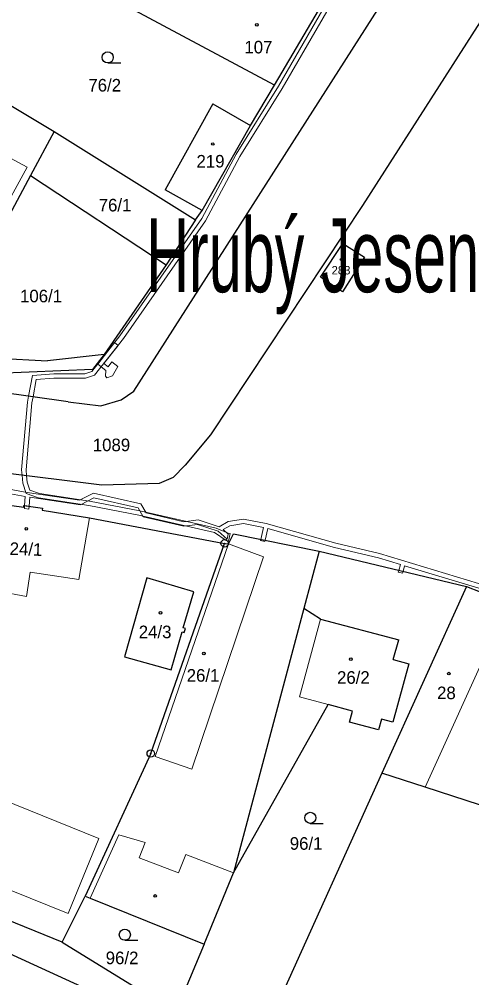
# Model space of a CAD drawing. Extents: x -694609 to -690140, y -1033292 to -1029794.
# Drawn here: x -692957.6 to -692896.4, y -1031318.8 to -1031189.2 of the extents above; entities that cross this region are included whole.
import ezdxf
from ezdxf.enums import TextEntityAlignment as Align

# ---------------------------------------------------------------- set-up
doc = ezdxf.new("R2010")
doc.units = 0
doc.header["$LTSCALE"] = 0.68
for name, color, linetype, lineweight in [('1', 7, 'Continuous', 25), ('13', 7, 'Continuous', 13), ('3', 7, 'Continuous', 25), ('4', 7, 'Continuous', 13), ('5', 7, 'Continuous', 25), ('7', 7, 'Continuous', 13), ('8', 7, 'Continuous', 25)]:
    doc.layers.add(name, color=color, linetype=linetype, lineweight=lineweight)
doc.layers.add('2', color=7, linetype='Continuous')

msp = doc.modelspace()

# ---------------------------------------------------------------- linework, layer by layer
at = {"layer": '1'}
for p, q in [((-692942.13, -1031239.46), (-692888.6, -1031155.82)), ((-692875.01, -1031157.97), (-692911.18, -1031214.36)), ((-692923.09, -1031198.13), (-692913.26, -1031181.38)), ((-692923.09, -1031198.13), (-692951.79, -1031182.73)), ((-692968.81, -1031194.86), (-692952.89, -1031204.36)), ((-692926.34, -1031203.55), (-692923.09, -1031198.13)), ((-692931.44, -1031200.65), (-692937.89, -1031212.25)), ((-692931.44, -1031200.65), (-692926.34, -1031203.55)), ((-692952.89, -1031204.36), (-692956.08, -1031210.31)), ((-692952.89, -1031204.36), (-692933.78, -1031216.33)), ((-692932.87, -1031215.04), (-692926.34, -1031203.55)), ((-692956.08, -1031210.31), (-692959.72, -1031217.1)), ((-692956.08, -1031210.31), (-692937.76, -1031222.38)), ((-692932.87, -1031215.04), (-692937.89, -1031212.25)), ((-692911.18, -1031214.36), (-692931.74, -1031245.37)), ((-692933.78, -1031216.33), (-692932.87, -1031215.04)), ((-692933.78, -1031216.33), (-692937.76, -1031222.38)), ((-692916.85, -1031224.06), (-692913.82, -1031219.5)), ((-692913.82, -1031219.5), (-692910.91, -1031221.36)), ((-692910.91, -1031221.36), (-692913.88, -1031226.03)), ((-692937.76, -1031222.38), (-692946.13, -1031234.51)), ((-692913.88, -1031226.03), (-692916.85, -1031224.06)), ((-692969.9, -1031234.55), (-692953.78, -1031235.37)), ((-692946.13, -1031234.51), (-692953.78, -1031235.37)), ((-692946.13, -1031234.51), (-692947.73, -1031236.57)), ((-692947.73, -1031236.57), (-692974.43, -1031237.64)), ((-692951.01, -1031240.92), (-692974.43, -1031237.64)), ((-692943.82, -1031240.64), (-692942.13, -1031239.46)), ((-692946.59, -1031241.46), (-692943.82, -1031240.64)), ((-692951.01, -1031240.92), (-692946.59, -1031241.46)), ((-692946.43, -1031252.19), (-692997.14, -1031245.89)), ((-692931.74, -1031245.37), (-692935.15, -1031249.49)), ((-692935.15, -1031249.49), (-692936.79, -1031251.14)), ((-692936.79, -1031251.14), (-692938.67, -1031251.96)), ((-692938.67, -1031251.96), (-692946.43, -1031252.19)), ((-692957.02, -1031255.21), (-692963.38, -1031254.29)), ((-692957.02, -1031255.21), (-692956.99, -1031254.92)), ((-692956.99, -1031254.92), (-692954.48, -1031255.31)), ((-692954.48, -1031255.31), (-692954.52, -1031255.58)), ((-692954.52, -1031255.58), (-692948.13, -1031256.59)), ((-692948.13, -1031256.59), (-692929.83, -1031260.05)), ((-692929.3, -1031260.1), (-692928.65, -1031258.76)), ((-692928.65, -1031258.76), (-692917.04, -1031261.11)), ((-692939.83, -1031288.46), (-692929.83, -1031260.05)), ((-692929.83, -1031260.05), (-692929.3, -1031260.1)), ((-692917.04, -1031261.11), (-692919.1, -1031268.86)), ((-692917.04, -1031261.11), (-692897.1, -1031265.9)), ((-692940.34, -1031264.73), (-692943.39, -1031275.4)), ((-692934, -1031266.59), (-692940.34, -1031264.73)), ((-692935.42, -1031271.46), (-692934, -1031266.59)), ((-692897.1, -1031265.9), (-692908.54, -1031291.14)), ((-692897.1, -1031265.9), (-692891.4, -1031268.11)), ((-692919.1, -1031268.86), (-692928.63, -1031304.59)), ((-692916.85, -1031270.31), (-692919.1, -1031268.86)), ((-692916.85, -1031270.31), (-692906.27, -1031273.08)), ((-692935.13, -1031271.55), (-692935.42, -1031271.46)), ((-692935.29, -1031272.09), (-692935.13, -1031271.55)), ((-692937.07, -1031277.16), (-692935.57, -1031272.01)), ((-692935.57, -1031272.01), (-692935.29, -1031272.09)), ((-692907.02, -1031275.74), (-692906.27, -1031273.08)), ((-692943.39, -1031275.4), (-692937.07, -1031277.16)), ((-692907.02, -1031275.74), (-692904.9, -1031276.32)), ((-692904.9, -1031276.32), (-692907.05, -1031284.23)), ((-692928.63, -1031304.59), (-692915.81, -1031281.85)), ((-692912.51, -1031282.74), (-692915.81, -1031281.85)), ((-692912.91, -1031284.22), (-692912.51, -1031282.74)), ((-692909, -1031285.28), (-692912.91, -1031284.22)), ((-692908.6, -1031283.81), (-692909, -1031285.28)), ((-692907.05, -1031284.23), (-692908.6, -1031283.81)), ((-692939.83, -1031288.46), (-692948.68, -1031307.75)), ((-692908.54, -1031291.14), (-692925.77, -1031329.14)), ((-692902.7, -1031293.03), (-692908.54, -1031291.14)), ((-692886.2, -1031298.35), (-692902.7, -1031293.03)), ((-692951.8, -1031313.97), (-692977.11, -1031303.75)), ((-692944.79, -1031321.99), (-692982.62, -1031304.77)), ((-692932.61, -1031314.23), (-692928.63, -1031304.59)), ((-692951.8, -1031313.97), (-692948.68, -1031307.75)), ((-692948.68, -1031307.75), (-692948.03, -1031308.01)), ((-692948.03, -1031308.01), (-692932.61, -1031314.23)), ((-692951.8, -1031313.97), (-692936.46, -1031323.39)), ((-692932.61, -1031314.23), (-692936.46, -1031323.39))]:
    msp.add_line(p, q, dxfattribs=at)
at = {"layer": '13'}
for points in [[(-692909.67, -1031175.99), (-692922.55, -1031198.25), (-692928.27, -1031207.44), (-692932.92, -1031216.14), (-692943.99, -1031231.99), (-692947.8, -1031236.81), (-692948.76, -1031237.14), (-692952.95, -1031237.12), (-692955.83, -1031237.35), (-692956.35, -1031240.17), (-692955.76, -1031240.26), (-692955.33, -1031237.91), (-692952.93, -1031237.72), (-692948.66, -1031237.74), (-692947.44, -1031237.31), (-692943.51, -1031232.35), (-692932.4, -1031216.46), (-692927.75, -1031207.74), (-692922.03, -1031198.55), (-692909.15, -1031176.29)], [(-692892.48, -1031266.37), (-692908.85, -1031261.41), (-692914.8, -1031260.02), (-692924.22, -1031257.36), (-692927.29, -1031256.76), (-692929.33, -1031257.11), (-692930.57, -1031257.82), (-692933.42, -1031256.88), (-692935.33, -1031257.14), (-692940.46, -1031255.93), (-692941.17, -1031254.73), (-692947.59, -1031253.26), (-692949.45, -1031254.21), (-692956.55, -1031253.16), (-692962.69, -1031252.04)], [(-692962.84, -1031252.62), (-692956.81, -1031253.72), (-692956.89, -1031254.94), (-692956.29, -1031255.03), (-692956.21, -1031253.82), (-692949.35, -1031254.83), (-692947.51, -1031253.9), (-692941.55, -1031255.25), (-692940.84, -1031256.45), (-692935.37, -1031257.74), (-692933.48, -1031257.5), (-692930.7, -1031258.41), (-692929.5, -1031259.48), (-692929.34, -1031258.82), (-692930.02, -1031258.2), (-692929.12, -1031257.68), (-692927.29, -1031257.37), (-692924.58, -1031257.9), (-692924.95, -1031259.51), (-692924.36, -1031259.63), (-692924, -1031258.05), (-692914.98, -1031260.6), (-692909.02, -1031261.99), (-692906.04, -1031262.91), (-692906.27, -1031263.7), (-692905.68, -1031263.84), (-692905.47, -1031263.08), (-692892.12, -1031267.1)]]:
    msp.add_lwpolyline(points, dxfattribs=at)
for points in [[(-692945.08, -1031235.52), (-692945.6, -1031236.18), (-692946.17, -1031235.72), (-692944.24, -1031233.29), (-692944.71, -1031232.92), (-692947.01, -1031235.82), (-692945.91, -1031236.7), (-692945.96, -1031237.46), (-692945.76, -1031237.66), (-692944.99, -1031237.4), (-692944.3, -1031236.14)], [(-692956.35, -1031240.17), (-692956.5, -1031240.97), (-692957.3, -1031250.13), (-692957.24, -1031250.85), (-692956.63, -1031250.92), (-692956.7, -1031250.13), (-692955.9, -1031241.05), (-692955.76, -1031240.26)], [(-692957.24, -1031250.85), (-692957.15, -1031251.92), (-692956.68, -1031253.33), (-692955.02, -1031253.88), (-692948.21, -1031254.93), (-692941.42, -1031256.23), (-692931.19, -1031258.58), (-692929.6, -1031259.67), (-692929.31, -1031259.74), (-692929.06, -1031258.7), (-692929.36, -1031258.66), (-692930.99, -1031258.02), (-692941.3, -1031255.65), (-692948.11, -1031254.33), (-692954.88, -1031253.3), (-692956.2, -1031252.85), (-692956.55, -1031251.8), (-692956.63, -1031250.92)], [(-692956.89, -1031254.94), (-692956.92, -1031255.33), (-692956.32, -1031255.42), (-692956.29, -1031255.03)], [(-692924.95, -1031259.51), (-692924.98, -1031259.65), (-692924.39, -1031259.78), (-692924.36, -1031259.63)], [(-692906.27, -1031263.7), (-692906.34, -1031263.94), (-692905.74, -1031264.08), (-692905.68, -1031263.84)]]:
    msp.add_lwpolyline(points, close=True, dxfattribs=at)
at = {"layer": '3'}
for p, q in [((-692945.643, -1031195.11), (-692943.893, -1031195.11)), ((-692918.233, -1031297.91), (-692916.483, -1031297.91)), ((-692943.333, -1031313.72), (-692941.583, -1031313.72))]:
    msp.add_line(p, q, dxfattribs=at)
for centre in [(-692945.6429, -1031194.3598), (-692918.2329, -1031297.1598), (-692943.3329, -1031312.9698)]:
    msp.add_circle(centre, 0.75, dxfattribs=at)
at = {"layer": '4'}
for p, q in [((-692969.81, -1031202.02), (-692956.54, -1031209.21)), ((-692956.54, -1031209.21), (-692960.42, -1031216.23)), ((-692949.57, -1031264.94), (-692948.13, -1031256.59)), ((-692939.22, -1031288.87), (-692929.3, -1031260.1)), ((-692929.3, -1031260.1), (-692924.55, -1031261.87)), ((-692924.55, -1031261.87), (-692934.28, -1031290.6)), ((-692956.65, -1031267.24), (-692956.14, -1031263.94)), ((-692956.14, -1031263.94), (-692949.57, -1031264.94)), ((-692962.43, -1031266.14), (-692956.65, -1031267.24)), ((-692891.4, -1031268.11), (-692902.7, -1031293.03)), ((-692939.22, -1031288.87), (-692934.28, -1031290.6)), ((-692944.15, -1031299.45), (-692948.03, -1031308.01)), ((-692944.15, -1031299.45), (-692940.57, -1031300.5)), ((-692940.57, -1031300.5), (-692941.38, -1031302.58)), ((-692941.38, -1031302.58), (-692936.09, -1031304.61)), ((-692936.09, -1031304.61), (-692935.08, -1031302.12)), ((-692928.63, -1031304.59), (-692935.08, -1031302.12))]:
    msp.add_line(p, q, dxfattribs=at)
msp.add_lwpolyline([(-692915.81, -1031281.85), (-692919.7, -1031280.79), (-692916.85, -1031270.31)], dxfattribs=at)
msp.add_lwpolyline([(-692971.82, -1031301.71), (-692967.72, -1031291.51), (-692946.84, -1031299.97), (-692950.98, -1031310.11)], close=True, dxfattribs=at)
at = {"layer": '5'}
for centre, radius in [((-692925.4668, -1031189.9492), 0.175), ((-692931.4368, -1031206.0592), 0.175), ((-692914.0546, -1031221.6794), 0.1172), ((-692956.6668, -1031258.0892), 0.175), ((-692938.4968, -1031269.4492), 0.175), ((-692932.6268, -1031274.9492), 0.175), ((-692912.7568, -1031275.6992), 0.175), ((-692899.4968, -1031277.6592), 0.175), ((-692939.2368, -1031307.7192), 0.175)]:
    msp.add_circle(centre, radius, dxfattribs=at)
at = {"layer": '8'}
for centre, radius in [((-692929.83, -1031260.0499), 0.5), ((-692929.83, -1031260.0499), 0.0303), ((-692939.83, -1031288.4599), 0.5), ((-692939.83, -1031288.4599), 0.0303)]:
    msp.add_circle(centre, radius, dxfattribs=at)

# ---------------------------------------------------------------- texts
at = {"layer": '2'}
for s, height, p in [('107', 1.7, (-692925.259, -1031193.815)), ('76/2', 1.7, (-692946.059, -1031198.965)), ('219', 1.7, (-692931.739, -1031209.245)), ('76/1', 1.7, (-692944.659, -1031215.175)), ('283', 1.14, (-692914.08, -1031223.695)), ('106/1', 1.7, (-692954.67, -1031227.465)), ('1089', 1.7, (-692945.14, -1031247.595)), ('26/1', 1.7, (-692932.749, -1031278.755)), ('26/2', 1.7, (-692912.409, -1031279.035)), ('28', 1.7, (-692899.819, -1031281.115)), ('96/1', 1.7, (-692918.799, -1031301.475)), ('96/2', 1.7, (-692943.709, -1031316.945))]:
    msp.add_text(s, height=height, dxfattribs=at).set_placement(p, align=Align.CENTER)
msp.add_text('24/1', height=1.7, rotation=358, dxfattribs=at).set_placement((-692958.944, -1031261.604))
msp.add_text('24/3', height=1.7, dxfattribs=at).set_placement((-692941.45, -1031272.875))
at = {"layer": '7', "width": 0.6}
msp.add_text('Hrubý Jeseník 648647', height=10, dxfattribs=at).set_placement((-692900.299, -1031226.093), align=Align.CENTER)

doc.saveas('drawing.dxf')
